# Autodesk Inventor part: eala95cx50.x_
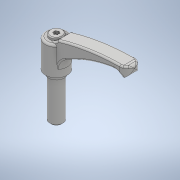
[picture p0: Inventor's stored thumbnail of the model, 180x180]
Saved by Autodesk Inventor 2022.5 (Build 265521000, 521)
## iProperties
Created: 2018-05
Part Number: eala95cx50.x_
Material: 一般
Document SubType Name: Modeling
Designer: imaocorp
Density: 1 g/cm^3
Appearance: 既定
Sending System: SOLIDWORKS 2016-2016286
MC: AMD64
MC_MODEL: AMD64 Family 21 Model 2 Stepping 0, AuthenticAMD
OS: Windows_NT
FRU: Parasolid Version 28.0, build 224,  7-29-2016
FORMAT: text
GUISE: transmit
KEY: eala95cx50
FILE: eala95cx50.x_t
DATE: Fri May 18 11:34:24 2018
Author: imaocorp
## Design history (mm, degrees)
feature "Base1"
node "ソリッド1"
